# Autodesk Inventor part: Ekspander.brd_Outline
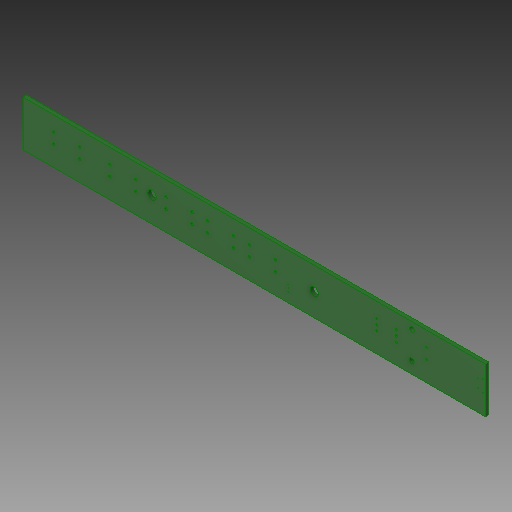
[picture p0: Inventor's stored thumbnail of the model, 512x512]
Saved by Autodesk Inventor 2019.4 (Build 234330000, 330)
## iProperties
Created: 2019-11
Part Number: Ekspander.brd_Outline
Material: Generic
Document SubType Name: Modeling
Designer: Willist
Density: 1 g/cm^3
Appearance: Board Outline
Author: Willist
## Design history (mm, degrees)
sketch "Sketch1"
  geometry: L1 (0, -21.946)-(222.301, -21.946); L2 (222.301, -21.946)-(222.301, 0); L3 (222.301, 0)-(0, 0); L4 (0, 0)-(0, -21.946); C1 r 0.6 at (68.73, -7.25); C2 r 0.6 at (81.23, -7.25); C3 r 0.6 at (68.73, -12.25); C4 r 0.6 at (81.23, -12.25); C5 r 0.6 at (41.71, -7.25); C6 r 0.6 at (54.21, -7.25); C7 r 0.6 at (41.71, -12.25); C8 r 0.6 at (54.21, -12.25); C9 r 0.51 at (179.45, -7.21); C10 r 0.51 at (179.45, -12.29); C11 r 0.51 at (179.45, -9.75); C12 r 1.145 at (186.94, -16.36); C13 r 1.145 at (186.94, -3.15); C14 r 0.51 at (193.93, -12.29); C15 r 0.51 at (193.93, -7.21); C16 r 0.6 at (14.68, -7.25); C17 r 0.6 at (27.18, -7.25); C18 r 0.6 at (14.68, -12.25); C19 r 0.6 at (27.18, -12.25); C20 r 0.25 at (220.96, -6.93); C21 r 0.25 at (220.96, -12.58); C22 r 0.6 at (108.76, -7.25); C23 r 0.6 at (121.26, -7.25); C24 r 0.6 at (108.76, -12.25); C25 r 0.6 at (121.26, -12.25); C26 r 0.6 at (88.64, -7.25); C27 r 0.6 at (101.14, -7.25); C28 r 0.6 at (88.64, -12.25); C29 r 0.6 at (101.14, -12.25); C30 r 0.51 at (170.08, -7.21); C31 r 0.51 at (170.08, -9.75); C32 r 0.51 at (170.08, -12.29); C33 r 2 at (61.976, -9.754); C34 r 2 at (140, -11); C35 r 0.225 at (218.76, -7.754); C36 r 0.225 at (218.76, -11.754); C37 r 0.2 at (127.5, -14.25); C38 r 0.2 at (127.5, -15.75); C39 r 0.2 at (127.5, -17.25)
  constraints: 39 centre point, 8 end point
extrude "Ekspander.brd_Outline" join sketch "Sketch1" distance "d0" = 1.6; taper "d1" = 0 deg
body "Solid1"
